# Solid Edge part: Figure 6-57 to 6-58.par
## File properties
Author: CADCIM
Template: normal.par
Last saved by: CADCIM
Revision: 7
Application: Solid Edge
Accuracy: 0.99
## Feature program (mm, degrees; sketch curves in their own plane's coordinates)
sketch for "unnamed Protrusion 1" plane through (0, 0, 0) normal (0, 0, 1) x-axis (1, 0, 0)
  line (-57.5394, -46.868) -> (57.5394, -46.868)
  line (57.5394, -46.868) -> (57.5394, 41.189)
  line (57.5394, 41.189) -> (-57.5394, 41.189)
  line (-57.5394, 41.189) -> (-57.5394, -46.868)
extrude "unnamed Protrusion 1" add finite 19.05 along +normal
sketch for "unnamed Cutout 1" plane through (0, -17.9367, 19.05) normal (0, 0, 1) x-axis (1, 0, 0)
  line (-52.7985, -13.2687) -> (-31.7897, -13.2687)
  line (-31.7897, -13.2687) -> (-31.7897, -0.8293)
  line (-31.7897, -0.8293) -> (-52.7985, -0.8293)
  line (-52.7985, -0.8293) -> (-52.7985, -13.2687)
extrude "unnamed Cutout 1" cut through along -normal
pattern "PatternOccurrence_9" of "unnamed Cutout 1" along a curve  XDirCount = 8; YDirCount = 2
pattern "unnamed Pattern 1"
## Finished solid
Body 1: solid body, 38 faces, 108 edges, 72 vertices.
  Faces by surface: plane 38
  Edges by curve: line 108
Bounding box of the edges (mm): 115.079 x 88.057 x 19.050, from (-57.5394, -46.868, 0) to (57.5394, 41.189, 19.05).
Planar faces by outward normal: +x 2, +y 2, +z 1, -x 2, -y 2, -z 1, oblique 28
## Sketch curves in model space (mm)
line (-47.821, -27.0372, 19.05) -> (-34.8186, -40.2964, 19.05)
spline (-47.821, -27.0372, 19.05) -> (43.5628, 9.9651, 19.05) -> (-43.116, 9.1379, 19.05)
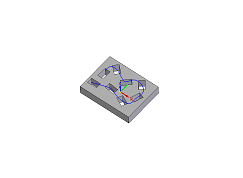
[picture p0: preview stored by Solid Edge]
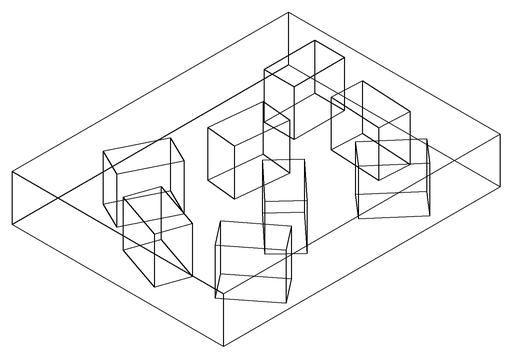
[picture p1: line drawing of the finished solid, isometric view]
